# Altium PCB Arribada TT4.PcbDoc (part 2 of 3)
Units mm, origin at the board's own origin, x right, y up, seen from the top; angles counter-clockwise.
Board outline 56 x 35 mm, 6 copper layers (Top Layer, L2GND, L3, L4, L5GND, Bottom Layer), stack 0.865 mm thick; 99 components, 88 nets, 417 pads, 769 vias.
Unrouted connection lines stored in the file: 31.
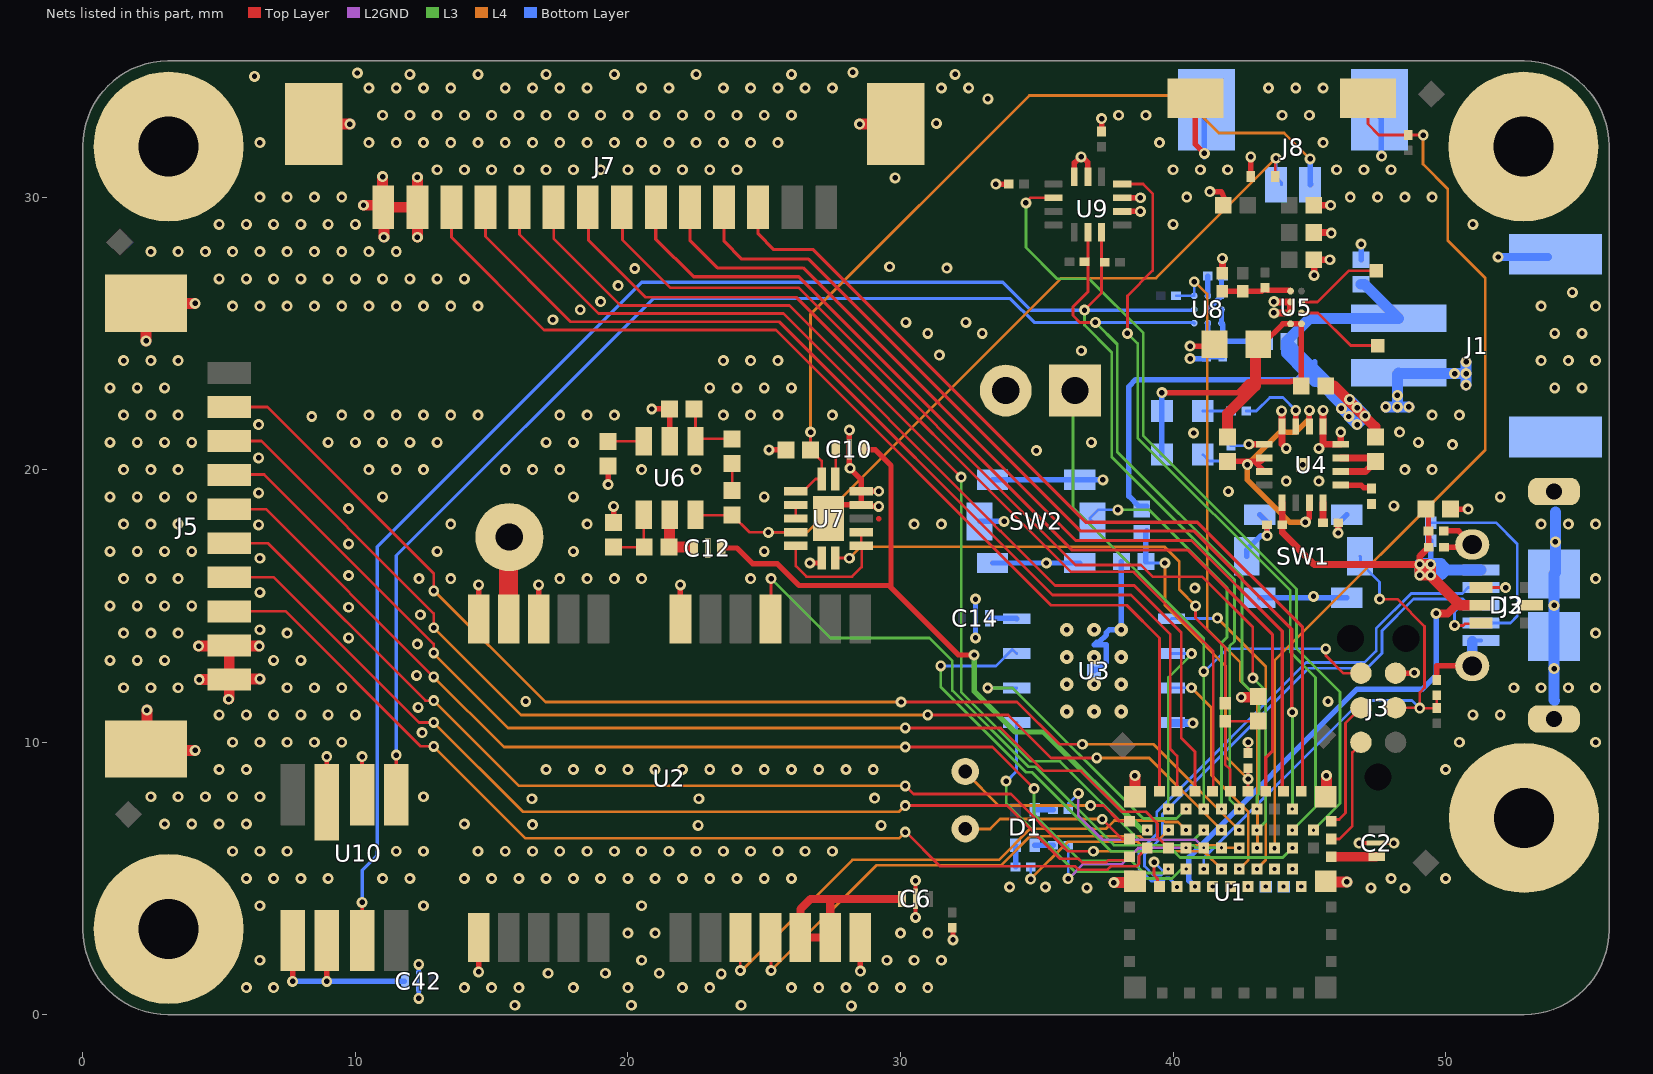
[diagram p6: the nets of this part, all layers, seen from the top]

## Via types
v1: diameter 0.4, hole 0.2, Top Layer to Bottom Layer, tented both sides, 631 vias
v2: diameter 0.23, hole 0.1, Top Layer to L2GND, tented top, 27 vias
v3: diameter 0.25, hole 0.125, L2GND to L3, 25 vias
v4: diameter 0.5, hole 0.2, Top Layer to Bottom Layer, 12 vias
v5: diameter 0.25, hole 0.125, L2GND to L3, tented both sides, 12 vias
v6: diameter 0.23, hole 0.1, Top Layer to L2GND, tented both sides, 12 vias
v7: diameter 0.23, hole 0.1, L5GND to Bottom Layer, tented both sides, 11 vias
v8: diameter 0.25, hole 0.125, L4 to L5GND, tented both sides, 11 vias
v9: diameter 0.3, hole 0.15, L3 to L4, tented both sides, 11 vias
v10: diameter 0.3, hole 0.15, L3 to L4, 11 vias
v11: diameter 0.4, hole 0.2, Top Layer to Bottom Layer, 5 vias
v12: diameter 1, hole 1, Top Layer to Bottom Layer, tented both sides, 1 vias

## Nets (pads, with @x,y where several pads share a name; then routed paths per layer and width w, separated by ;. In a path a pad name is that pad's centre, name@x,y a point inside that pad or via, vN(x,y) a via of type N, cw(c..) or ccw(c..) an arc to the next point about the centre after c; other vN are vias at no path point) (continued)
GND: C1.1 C2.3 C3.1 C4.1 C5.1 C6.3 C8.1 C9.1 C10.3 C11.1 C12.3 C14.3 C19.1 C22.1 C24.1 C30.1 C31.1 C32.1 C33.1 C34.1 C35.1 C36.1 C42.3 C43.1 C45.1 D2.1 D3.2 J1.2 J1.3 J1.4 J2.5 J2.G1 J2.G2 J2.G3 J2.G4 J2.G5 J2.G6 J3.5 J4.2 J5.9 J5.10 J5.11 J5.12 J7.13 J7.14 J7.15 J7.16 J8.3 J8.4 MH1.1 MH2.1 MH3.1 MH4.1 R11.1 R13.1 R18.1 R20.1 R21.1 R22.1 R24.1 R47.1 SW1.1 SW1.G1 SW1.G2 SW1.G3 SW1.G4 SW2.1 SW2.G1 SW2.G2 SW2.G3 SW2.G4 SW3.1 U1.1 U1.7 U1.14 U1.16 U1.18 U1.21 U1.23 U1.24 U1.25 U1.31 U2.7 U2.10 U2.12 U2.13 U2.24 U3.4 U3.9 U4.4 U4.5 U4.8 U4.17 U5.B2 U5.C2 U6.2 U7.7 U7.12 U7.13 U7.15 U8.B2 U8.C1 U9.2 U9.3 U9.6 U9.7 U10.2 U10.3 | length 118.3
  Top Layer w0.1: C45.1@42.75,9.605 v1(42.75,10)
  Top Layer w0.15: U10.3@8.95,7.8 v1(8.95,9.475) ; U10.2@10.25,8.075 v1(10.25,9.475) ; v1(30.55,3.575) C6.3@30.55,4.25 v1(30.55,4.925) ; v1(46.825,6.3) C2.3@47.475,6.3 v1(48.1,6.3)
  Top Layer w0.2: v1(14.525,1.575) U2.13@14.525,2.833 ; U2.12@14.525,14.517 v1(14.525,15.775) ; U2.10@16.725,14.517 v1(16.725,15.775) ; v1(19.275,19.455) R21.1@19.275,20.13 ; R20.1@19.475,18.055 v1(19.475,18.65) ; v1(20.875,22.225) 20.88,22.23 C9.1@21.525,22.23 21.53,22.225 U6.2@21.53,21.045 ; U2.7@21.925,14.517 v1(21.925,15.775) ; v1(25.175,20.725) R22.1@25.8,20.725 ; v1(26.675,16.575) 27.025,16.575 27.109,16.659 U7.7@27.109,16.755 ; U7.15@27.359,18.205 U7.15@27.447,18.294 ; U7.15@27.536,18.205 U7.15@27.447,18.294 ; v1(28.125,21.45) C10.3@28.125,20.75 28.125,20.075 v1(28.15,20.05) 28.559,19.641 U7.13@28.559,19.205 ; v1(28.525,1.6) U2.24@28.525,2.833 ; 29.195,18.205 29.2,18.2 ; v1(29.2,19.205) U7.13@28.559,19.205 ; v1(29.201,18.651) 28.613,18.651 U7.12@28.559,18.705 ; C5.1@31.9,3.195 31.925,3.17 v1(31.925,2.75) ; v1(33.5,30.475) C36.1@33.97,30.475 ; U9.7@36.375,30.738 36.375,31.25 36.6,31.475 v1(36.625,31.475) 36.675,31.475 36.875,31.275 U9.6@36.875,30.738 ; C35.1@37.375,32.405 v1(37.375,32.875) ; U9.2@38.138,29.475 v1(38.8,29.475) ; U9.3@38.138,29.975 v1(38.8,29.975) ; v1(40.625,24.53) 41.455,24.53 C24.1@41.525,24.6 ; SW3.1@40.817,33.627 40.817,31.935 v1(41.15,31.602) ; v1(41.35,30.2) 41.775,30.2 41.91,29.897 C8.1@41.84,29.714 ; U1.14@41.45,4.7 v6(41.455,4.7) ; D2.1@42.85,30.725 v1(42.85,31.475) ; C43.1@43.445,17.975 43.445,17.58 v1(43.45,17.575) ; J3.5@48.16,12.535 48.865,12.535 v1(48.85,12.55) ; C19.1@49.675,12.28 49.675,12.8 J2.G1@50.975,12.8 ; C32.1@49.93,17.75 50.475,17.75 J2.G2@50.975,17.25 50.875,17.15 C31.1@49.935,17.15 ; C30.1@50.175,18.55 v1(50.825,18.55) ; U7.15@27.447,18.294 27.859,18.705 U7.12@28.559,18.705 ; U7.12@28.559,18.705 U7.13@28.559,19.205
  Top Layer w0.25: R13.1@41.809,27.205 v1(41.809,27.75) ; v1(43.7,25.75) U5.B2@44.309,25.75 U5.C2@44.309,26.15 43.7,26.15 v1(43.7,26.165) ; v1(43.982,22.156) 43.986,22.156 44,22.17 U4.8@44,21.582 44,20.932 v11(44.15,20.782) ; C4.1@45.159,28.7 45.775,28.7 v1(45.8,28.675) ; C3.1@45.159,29.7 v1(45.775,29.7) ; v1(45.175,27.125) 45.175,27.684 C1.1@45.159,27.7 v1(45.75,27.7) ; v11(45.35,20.782) 45.5,20.932 ; v1(45.5,22.175) U4.5@45.5,21.582 45.5,20.932 ; v1(46.055,17.675) R11.1@46.055,18.05 ; v1(46.15,21.375) U4.4@46.15,20.932 45.5,20.932
  Top Layer w0.4: J5.12@2.325,9.75 J5.12@2.35,9.775 ; v1(2.325,24.725) J5.11@2.325,26.1 v1@4.1,26.1 ; v1(2.35,11.175) J5.12@2.35,9.775 ; v1(4.125,9.7) 2.425,9.7 J5.12@2.35,9.775 ; v1(4.25,13.525) 5.35,13.525 J5.9@5.375,13.55 ; v1(4.275,12.3) J5.10@5.375,12.3 ; v1(5.35,11.575) 5.375,11.6 J5.10@5.375,12.3 ; v1(6.475,13.525) 5.4,13.525 J5.9@5.375,13.55 ; v1(6.5,12.325) J5.10@5.4,12.325 ; J7.15@8.475,32.675 v1(9.8,32.675) ; v1(10.3,29.7) 10.95,29.7 J7.14@11,29.65 ; v1(11,30.75) J7.14@11,29.65 ; v1(11.05,28.525) 11.05,29.6 J7.14@11.025,29.625 ; v1(12.275,28.525) J7.13@12.275,29.625 ; v1(12.275,30.725) J7.13@12.275,29.625 ; v1(28.5,32.675) J7.16@29.825,32.675 ; v1(37.825,4.85) 38.55,4.85 U1.7@38.6,4.9 ; U1.1@38.6,8 v1(38.6,8.775) ; v1(42.5,11.65) 43.1,11.65 C11.1@43.125,11.675 ; U1.25@45.6,4.9 45.625,4.875 v1(46.375,4.875) ; U1.31@45.6,8 45.625,8.025 v1(45.625,8.775) ; J5.10@5.375,12.3 J5.10@5.4,12.325 ; J5.9@5.375,13.55 5.375,12.35 J5.10@5.4,12.325 ; J7.14@11,29.65 J7.14@11.025,29.625 ; J7.14@11.025,29.625 J7.13@12.275,29.625
  Bottom Layer w0.1: U3.4@39.94,10.72 U3.4@39.96,10.7
  Bottom Layer w0.15: v1(12.325,0.6) C42.3@12.325,1.225 v1(12.325,1.85) ; J2.5@50.975,13.7 51,13.725 J2.5@51.3,13.725
  Bottom Layer w0.2: v1(32.75,13.825) C14.3@32.75,14.55 v1@32.75,15.175 ; SW2.1@32.9,18.1 v1(33.8,18.1) ; SW2.G1@33.375,16.575 SW2.G2@36.575,16.575 ; SW2.G4@33.375,19.625 SW2.G3@36.575,19.625 v1(37.425,19.625) ; U3.9@37.1,12.625 37.1,12.675 37.286,12.675 37.55,12.939 37.55,13.575 37.1,13.575 37.2,13.675 37.286,13.675 37.55,13.939 37.55,14.025 37.65,14.125 v4(38.1,14.125) R47.1@38.1,16.625 ; v1(40.625,24.075) 41.155,24.075 C33.1@41.225,24.145 C34.1@41.825,24.145 ; v1@41.15,31.475 41.15,33.125 J8.3@41.225,33.2 ; U8.B2@41.275,25.875 U8.C1@41.775,26.375 R24.1@41.775,27.045 ; v1(41.809,27.75) 41.83,27.729 R24.1@41.83,27.1 ; SW1.1@42.7,16.825 42.7,17.05 43.225,17.575 v1(43.45,17.575) 43.45,18.075 SW1.G4@43.175,18.35 ; SW1.G1@43.175,15.3 SW1.G2@46.375,15.3 ; v1(46.055,17.675) 46.055,18.03 SW1.G3@46.375,18.35 ; C22.1@46.9,27.7 v1(46.9,28.275) ; J8.4@47.575,33.2 47.575,32.95 47.64,32.885 47.64,31.51 v1@47.675,31.475
  Bottom Layer w0.3: U3.4@39.96,10.7 v1(40.725,10.7) ; v1(51.925,27.8) J1.4@53.75,27.8
  Bottom Layer w0.4: v1(47.8,22.3) v1(48.225,22.3) ; v1(48.65,22.3) v1(48.225,22.3) ; v1(50.75,23.1) v1(50.75,23.525) ; v1(50.75,23.95) v1(50.75,23.525) ; J2.G1@50.975,12.8 J2.5@50.975,13.7 ; 54,11.525 53.975,11.55 J2.G5@53.975,13.875 J2.G6@53.975,16.175 54.025,16.225 54.025,18.45 ; v1(48.225,22.3) v1(48.225,22.725) 48.225,23.5 J1.2@48.275,23.55 48.3,23.525 v1(50.325,23.525) v1(50.75,23.525)
  other v1: 28.2,0.325 15.85,0.35 20.125,0.35 24.15,0.35 6,1 7,1 14,1 15,1 16,1 18,1 20,1 22,1 23,1 26,1 27,1 28,1 29,1 30,1 31,1 23.425,1.5 17.075,1.525 19.175,1.525 21.15,1.525 6.5,2 20.5,2 29.5,2 30.5,2 31.5,2 20,3 21,3 30,3 31,3 6.5,4 12.5,4 20.5,4 36.84,4.658 47.259,4.658 48.5,4.642 34,4.689 35.313,4.689 6,5 7,5 8,5 9,5 11,5 12,5 14,5 15,5 16,5 17,5 18,5 19,5 20,5 21,5 22,5 23,5 24,5 25,5 26,5 48,5 50,5 5.5,6 6.5,6 7.5,6 11.5,6 12.5,6 14.5,6 15.5,6 16.5,6 17.5,6 18.5,6 19.5,6 20.5,6 21.5,6 22.5,6 23.5,6 24.5,6 25.5,6 26.5,6 27.5,6 22.575,6.95 29.291,6.95 16.5,6.975 3,7 4,7 5,7 6,7 14,7 16.475,7.927 22.6,7.927 29.05,7.95 2.5,8 3.5,8 4.5,8 5.5,8 6.5,8 12.5,8 5,9 6,9 17,9 18,9 19,9 20,9 21,9 22,9 23,9 24,9 25,9 26,9 27,9 28,9 29,9 50,9 5.5,10 6.5,10 7.5,10 8.5,10 9.5,10 50.5,10 55.5,10 12.447,10.35 5,11 6,11 7,11 8,11 9,11 10,11 51,11 52,11 12.3,11.275 16.25,11.5 45.683,11.5 1.5,12 2.5,12 3.5,12 7.5,12 8.5,12 9.5,12 52.5,12 53.5,12 54.5,12 55.5,12 12.25,12.45 53.975,12.7 1,13 2,13 3,13 7,13 8,13 12.275,13.6 9.75,13.825 1.5,14 2.5,14 3.5,14 7.5,14 55.5,14 6.5,14.125 12.389,14.675 9.75,14.95 1,15 2,15 3,15 4,15 53.975,15.021 32.75,15.25 45.15,15.35 6.5,15.5 40.8,15.658 1.5,16 2.5,16 3.5,16 12.335,16 13.5,16 17.5,16 18.5,16 19.5,16 20.5,16 24.5,16 55.5,16 9.75,16.117 35.35,16.575 6.5,16.75 1,17 2,17 3,17 4,17 13,17 18,17 25,17 9.75,17.275 54.025,17.35 6.45,17.975 1.5,18 2.5,18 3.5,18 13.5,18 18.5,18 30.5,18 31.5,18 53.5,18 54.5,18 55.5,18 9.75,18.575 48.1,18.667 1,19 2,19 3,19 4,19 11,19 18,19 25,19 52,19 6.45,19.15 42.025,19.2 1.5,20 2.5,20 3.5,20 10.5,20 11.5,20 12.5,20 15.5,20 16.5,20 17.5,20 20.5,20 22.5,20 48.5,20 49.5,20 6.45,20.432 34.983,20.7 50.25,20.92 1,21 2,21 3,21 4,21 9,21 10,21 11,21 12,21 13,21 17,21 18,21 37,21 49,21 40.75,21.344 48.309,21.375 6.45,21.65 8.4,21.95 1.5,22 2.5,22 3.5,22 9.5,22 10.5,22 11.5,22 12.5,22 13.5,22 14.5,22 17.5,22 18.5,22 19.5,22 23.5,22 24.5,22 25.5,22 27.5,22 49.5,22 50.5,22 1,23 2,23 3,23 23,23 24,23 25,23 26,23 54,23 55,23 1.5,24 2.5,24 3.5,24 23.5,24 24.5,24 25.5,24 53.5,24 54.5,24 55.5,24 31.423,24.2 36.637,24.362 31,25 33,25 54,25 55,25 30.2,25.4 32.4,25.4 17.25,25.5 18.25,25.867 5.5,26 6.5,26 7.5,26 8.5,26 9.5,26 10.5,26 11.5,26 12.5,26 13.5,26 14.5,26 53.5,26 55.5,26 4.125,26.1 19,26.165 54.65,26.5 19.638,26.75 5,27 6,27 7,27 8,27 9,27 10,27 11,27 12,27 13,27 14,27 20.25,27.38 31.7,27.394 29.6,27.444 2.5,28 3.5,28 4.5,28 5.5,28 6.5,28 7.5,28 8.5,28 9.5,28 10.5,28 11.5,28 5,29 6,29 7,29 8,29 9,29 10,29 40,29 51,29 6.5,30 7.5,30 8.5,30 9.5,30 40.5,30 46.5,30 47.5,30 48.5,30 49.5,30 29.8,30.7 13,31 14,31 15,31 16,31 17,31 18,31 19,31 20,31 21,31 22,31 23,31 24,31 40,31 41,31 42,31 46,31 47,31 48,31 47.65,31.5 6.5,32 10.5,32 11.5,32 12.5,32 13.5,32 14.5,32 15.5,32 16.5,32 17.5,32 18.5,32 19.5,32 20.5,32 21.5,32 22.5,32 23.5,32 24.5,32 25.5,32 39.5,32 45.5,32 31.316,32.7 11,33 12,33 13,33 14,33 15,33 16,33 17,33 18,33 19,33 20,33 21,33 22,33 23,33 24,33 25,33 26,33 38,33 39,33 44,33 45,33 33.208,33.6 10.5,34 11.5,34 12.5,34 13.5,34 15.5,34 16.5,34 17.5,34 18.5,34 20.5,34 21.5,34 23.5,34 24.5,34 25.5,34 26.5,34 27.5,34 31.5,34 32.5,34 43.5,34 44.5,34 45.5,34 6.3,34.425 12,34.5 14.5,34.5 17,34.5 19.5,34.5 22.5,34.5 26,34.5 32,34.5 10.075,34.55 28.25,34.575
  other v4: 36.1,11.125 37.1,11.125 38.1,11.125 36.1,12.125 37.1,12.125 38.1,12.125 36.1,13.125 37.1,13.125 38.1,13.125 36.1,14.125 37.1,14.125
  other v5: 41.455,4.7 42.1,4.7 42.75,4.7 44.701,4.7 43.725,5.35 44.375,5.35
  other v6: 42.1,4.7 42.75,4.7 44.701,4.7 43.725,5.35 44.375,5.35
  other v7: 41.455,4.7 42.1,4.7 42.75,4.7 44.701,4.7 43.725,5.35 44.375,5.35
  other v8: 41.455,4.7 42.1,4.7 42.75,4.7 44.701,4.7 43.725,5.35 44.375,5.35
  other v9: 41.455,4.7 42.1,4.7 42.75,4.7 44.701,4.7 43.725,5.35 44.375,5.35
  other v11: 44.15,19.582 45.35,19.582 44.75,20.182
NetANT1_1: ANT1.1 U2.11 | length 3.4
  Top Layer w0.121: ANT1.1@15.625,17.475 ANT1.1@15.65,17.5
  Top Layer w0.7: U2.11@15.625,14.067 ANT1.1@15.625,17.475
  other v12: 15.65,17.525
NetC2_2: C2.2 U1.26 | length 1.7
  Top Layer w0.35: U1.26@45.8,5.8 C2.2@47.459,5.8
NetC6_1: C6.1 U2.22 U2.23 | length 8.3
  Top Layer w0.3: U2.22@26.325,2.383 U2.22@26.325,2.833 ; U2.23@27.425,2.383 U2.23@27.425,2.833 ; C6.1@30.05,4.25 27.425,4.25 ; U2.22@26.325,2.833 26.325,3.875 26.7,4.25 27.425,4.25 ; U2.22@26.325,2.833 U2.23@27.425,2.833 ; U2.23@27.425,2.833 27.425,4.25
NetC7_1: C7.1 R12.1 R13.2 U5.D2 | length 2.6
  Top Layer w0.2: R13.2@41.809,26.545 R12.1@42.559,26.545 43.25,26.545 C7.1@43.375,26.67 43.47,26.575 44.284,26.575 U5.D2@44.309,26.55
NetC9_2: C9.2 R17.2 U6.1 | length 2.6
  Top Layer w0.1: C9.2@22.425,22.23 22.48,22.175 U6.1@22.48,21.045 22.566,21.13 R17.2@23.825,21.13
NetC10_1: C10.1 U7.14 | length 1.1
  Top Layer w0.1: U7.14@27.609,19.655 27.625,19.671 C10.1@27.625,20.75
NetC10_2: C10.2 C12.1 U1.3 | length 26.4
  Top Layer w0.2: C12.1@23.425,17.125 24,17.125 24.575,16.55 25.475,16.55 26.275,15.75 29.575,15.75 ; C10.2@28.625,20.725 29.075,20.725 29.65,20.15 29.65,15.75 29.575,15.75 ; v1(32.7,13.2) 32.125,13.2 29.575,15.75
  L3 w0.2: v1(32.7,13.2) 32.7,11.875 34.2,10.375 35.25,10.375 38.85,6.775 v6(39.05,6.775)
  other v5: 39.05,6.775
NetC11_2: C11.2 R25.2 U1.40 | length 3.9
  Top Layer w0.1: U1.40@42.1,8.2 42.1,9 41.91,9.19 R25.2@41.91,10.77 43.12,10.77 C11.2@43.125,10.775
NetC12_2: C12.2 R19.2 U6.5 | length 2.1
  Top Layer w0.4: U6.5@21.53,18.345 21.53,17.186 R19.2@21.5,17.155 C12.2@22.35,17.155
NetC14_2: C14.2 U3.8 | length 1
  Bottom Layer w0.2: C14.2@33.25,14.55 34.24,14.55 U3.8@34.26,14.53
NetC19_2: C19.2 J3.3 R10.1 SW1.2 U1.13 | length 19.9
  Top Layer w0.1: v1(47.575,15.25) 48.225,15.25 49.225,14.25 49.225,12 49.05,11.825 v1(49.05,11.25) ; J3.3@48.16,11.265 49.035,11.265 v1(49.05,11.25) ; R10.1@49.675,11.205 49.63,11.25 v1(49.05,11.25) ; R10.1@49.675,11.255 C19.2@49.675,11.72
  Bottom Layer w0.1: v6(41.125,5.35) 41.125,5.75 46.908,11.533 48.767,11.533 v1(49.05,11.25) ; SW1.2@46.85,16.825 46.875,16.8 46.875,16.575 47.575,15.875 v1(47.575,15.25)
  other v5: 41.125,5.35
  other v7: 41.125,5.35
  other v8: 41.125,5.35
  other v9: 41.125,5.35
NetC33_2: C33.2 U8.B3 | length 0.7
  Bottom Layer w0.2: C33.2@41.225,24.705 41.275,24.755 U8.B3@41.275,25.375
NetC34_2: C34.2 R15.1 U8.C2 U8.C3 | length 2.6
  Bottom Layer w0.2: U8.C2@41.775,25.875 U8.C3@41.775,25.375 41.775,25.363 41.825,25.313 C34.2@41.825,24.705 ; C34.2@41.83,24.7 C34.2@41.825,24.705 ; R15.1@43.25,24.7 43.245,24.705 C34.2@41.825,24.705
NetC42_1: C42.1 U10.5 U10.6 | length 7.1
  Top Layer w0.2: v1(7.7,1.225) U10.5@7.7,2.725 ; v1(8.95,1.225) U10.6@8.95,2.725
  Bottom Layer w0.2: v1(7.7,1.225) v1(8.95,1.225) C42.1@11.8,1.225
NetC45_2: C45.2 R46.1 R47.2 U1.38 | length 11.9
  Top Layer w0.1: U1.38@42.75,8.2 C45.2@42.75,9.045
  L4 w0.1: v1(39.7,16.575) 39.7,15.025 41.925,12.8 41.925,9.475 v1(42.75,8.65)
  Bottom Layer w0.1: R47.2@39,16.625 39.05,16.575 v1(39.7,16.575)
  Bottom Layer w0.2: R47.2@39,16.625 39,17.725 R46.1@39.025,17.75
NetD1_2: D1.2 R3.2 | length 0.7
  Bottom Layer w0.2: D1.2@34.925,7.525 R3.2@35.595,7.525
NetD1_3: D1.3 R4.2 | length 0.7
  Bottom Layer w0.2: D1.3@34.925,6.225 R4.2@35.595,6.225
NetD1_4: D1.4 R5.2 | length 0.8
  Bottom Layer w0.2: R5.2@34.22,5.425 34.225,5.43 D1.4@34.225,6.225
NetD2_2: D2.2 J8.1 R16.1 U6.6 U7.5 | length 30.1
  Top Layer w0.1: U6.6@22.48,18.345 22.495,18.33 R16.1@23.825,18.33 24.45,17.705 U7.5@26.159,17.705 ; D2.2@43.75,30.75 43.75,31.45 v1(43.775,31.425)
  L4 w0.1: v1(25.15,17.7) 26.575,17.7 35.9,27.025 39.375,27.025 v1(43.775,31.425)
  Bottom Layer w0.1: v1(43.775,31.425) 43.775,30.65 43.858,30.65 43.975,30.533 J8.1@43.975,30.45
NetD5_2: D5.2 R26.2 | length 1.1
  Bottom Layer w0.1: D5.2@41.091,20.55 41.321,20.32 R26.2@42.125,20.32
NetD6_2: D6.2 R27.2 | length 1
  Bottom Layer w0.1: D6.2@41.091,22.15 R27.2@42.12,22.15
NetJ2_4: J2.4 R14.1 | length 7.6
  Bottom Layer w0.102: R14.1@49.45,18.055 51.845,18.055 52.625,17.275 52.625,14.625 52.375,14.375 J2.4@51.3,14.375
NetJ3_2: J3.2 U1.28 | length 4.2
  Top Layer w0.1: U1.28@45.8,6.45 46.1,6.45 46.575,6.925 46.575,9.624 46.89,9.939 J3.2@46.89,9.995
NetJ3_4: J3.4 U1.30 | length 4.7
  Top Layer w0.1: U1.30@45.8,7.1 45.866,7.166 46.091,7.166 46.325,7.4 46.325,10.7 J3.4@46.89,11.265
NetJ3_6: J3.6 J4.1 U1.43 | length 23.1
  Top Layer w0.1: v1(45.6,13.425) 45.6,13.175 46.24,12.535 J3.6@46.89,12.535
  L3 w0.1: 36.325,21.95 36.325,18.604 41.125,13.804 v2(41.125,7.55) ; J4.1@36.425,22.85 J4.1@36.475,22.9
  Bottom Layer w0.1: v1(41.125,12.6) 41.15,12.6 41.975,13.425 v1(45.6,13.425)
  other v3: 41.125,7.55
NetJ5_2: J5.2 U1.52 | length 43.9
  Top Layer w0.1: J5.2@5.375,22.3 6.775,22.3 12.875,16.2 v1(12.875,15.55) ; v1(30.025,11.475) 34.275,11.475 35.825,9.925 v1(36.675,9.925)
  L4 w0.1: v1(12.875,15.55) 12.875,15.575 16.975,11.475 v1(30.025,11.475) ; v1(36.675,9.925) 39.275,9.925 v10(42.425,6.775)
  other v2: 42.425,6.775
  other v3: 42.425,6.775
NetJ5_3: J5.3 U1.53 | length 42.7
  Top Layer w0.1: J5.3@5.375,21.05 6.55,21.05 12.875,14.725 v1@12.875,14.205 ; v1(31,11) 33.95,11 35.525,9.425 v1(37.2,9.425)
  L4 w0.1: v1(12.875,14.2) 12.875,14.205 16.08,11 v1(31,11) ; v1@37.125,9.425 v1(37.2,9.425) 39.125,9.425 v10(41.775,6.775)
  other v2: 41.775,6.775
  other v3: 41.775,6.775
NetJ5_4: J5.4 U1.64 | length 40.6
  Top Layer w0.1: J5.4@5.375,19.825 6.656,19.825 12.875,13.606 v1(12.875,13.275) ; v1(30.175,10.525) 33.675,10.525 35.25,8.95 36.625,8.95 38.125,7.45 38.15,7.45 39,7.45 39.432,7.018 39.432,6.519 U1.64@39.825,6.125
  L4 w0.1: v1(12.875,13.275) 12.875,13.25 15.6,10.525 v1(30.175,10.525)
NetJ5_5: J5.5 U1.9 | length 40.6
  Top Layer w0.1: J5.5@5.375,18.55 6.725,18.55 v1(12.875,12.4) ; v1(30.175,9.825) 33.375,9.825 v1(34.9,8.3)
  L3 w0.1: v1(34.9,8.3) 34.9,7.35 36.6,5.65 38.475,5.65 38.925,5.2 39.675,5.2 v2(39.825,5.35)
  L4 w0.1: v1(12.875,12.4) 15.45,9.825 v1(30.175,9.825)
  other v3: 39.825,5.35
NetJ5_6: J5.6 U1.15 | length 41.3
  Top Layer w0.1: J5.6@5.375,17.3 6.8,17.3 12.575,11.525 v1(12.875,11.525) ; v1(30.175,8.4) 30.475,8.1 34.05,8.1 36.15,6 v1(37.075,6)
  L4 w0.1: v1(12.875,11.525) 16,8.4 v1(30.175,8.4) ; v1(37.075,6) 41.125,6 v10(41.775,5.35)
  other v2: 41.775,5.35
  other v3: 41.775,5.35
NetJ5_7: J5.7 U1.6 | length 37.6
  Top Layer w0.1: J5.7@5.375,16.05 7.01,16.05 12.335,10.725 v1(12.875,10.725) ; v1(30.175,7.675) 33.9,7.675 35.85,5.725 36.525,5.725 36.65,5.6 37.55,5.6 37.625,5.675 38.275,5.675 U1.6@38.4,5.8
  L4 w0.1: v1(12.875,10.725) 16.15,7.45 29.95,7.45 v1(30.175,7.675)
NetJ5_8: J5.8 U1.5 | length 38.4
  Top Layer w0.1: J5.8@5.375,14.8 7.45,14.8 12.4,9.85 v1(12.875,9.85) ; v1(30.175,6.7) 30.2,6.7 31.45,5.45 36.4,5.45 36.525,5.325 37.6,5.325 37.725,5.45 38.662,5.45 38.75,5.538 38.75,5.825 39.025,6.1 39.05,6.1 39.075,6.075 39.075,6.1 U1.5@39.05,6.125
  L4 w0.1: v1(12.875,9.85) 16.25,6.475 29.95,6.475 v1(30.175,6.7)
NetJ7_3: J7.3 U1.32 | length 33
  Top Layer w0.121: J7.3@24.775,29.625 24.775,28.65 25.35,28.075 26.8,28.075 36.8,18.075 40.892,18.075 44.75,14.217 44.75,8.25 U1.32@44.7,8.2
NetJ7_4: J7.4 U1.33 | length 34.6
  Top Layer w0.121: J7.4@23.525,29.625 23.525,28.375 24.175,27.725 26.625,27.725 36.6,17.75 40.75,17.75 44.35,14.15 44.35,11.125 v1(44.375,11.1)
  L3 w0.102: v2(44.375,7.55) 44.4,7.575 44.375,7.6 v1(44.375,11.1)
  other v3: 44.375,7.55
NetJ7_5: J7.5 U1.34 | length 34.8
  Top Layer w0.121: J7.5@22.275,29.625 22.275,28.41 23.285,27.4 26.425,27.4 36.425,17.4 40.675,17.4 44,14.075 44,8.25 U1.34@44.05,8.2
NetJ7_6: J7.6 U1.36 | length 35.7
  Top Layer w0.121: J7.6@21.025,29.625 21.025,28.457 22.407,27.075 26.275,27.075 36.3,17.05 40.55,17.05 43.645,13.955 43.645,9.67 43.4,9.425 U1.36@43.4,8.2
NetJ7_7: J7.7 U1.51 | length 38
  Top Layer w0.1: J7.7@19.8,29.6 19.8,28.425 21.55,26.675 26.25,26.675 36.425,16.5 38.825,16.5 39.25,16.075 41.067,16.075 42.925,14.217 v1(42.925,12.35)
  Top Layer w0.2: J7.7@19.775,29.625 J7.7@19.8,29.6
  L3 w0.1: v1(42.925,12.35) 43.401,11.874 43.401,7.101 v3(43.075,6.775)
  other v2: 43.075,6.775
NetJ7_8: J7.8 U1.42 | length 35.5
  Top Layer w0.1: J7.8@18.55,29.6 18.55,28.414 20.639,26.325 26.175,26.325 36.25,16.25 38.55,16.25 41.475,13.325 41.475,8.225 U1.42@41.45,8.2
  Top Layer w0.2: J7.8@18.525,29.625 J7.8@18.55,29.6
NetJ7_9: J7.9 U1.54 | length 38.9
  Top Layer w0.1: J7.9@17.275,29.625 17.275,28.475 19.725,26.025 25.925,26.025 v1(32.225,19.725)
  L3 w0.1: v1(32.225,19.725) 32.232,19.725 32.225,19.718 32.225,11.85 34.775,9.3 35.85,9.3 38.725,6.425 40.775,6.425 v2(41.125,6.775)
  other v3: 41.125,6.775
NetJ7_10: J7.10 U1.44 | length 37.3
  Top Layer w0.1: J7.10@16.025,29.625 16.025,28.625 18.925,25.725 25.7,25.725 33.45,17.975 33.45,17.955 33.655,17.75 33.675,17.75 35.675,15.75 38.575,15.75 40.3,14.025 40.3,10.15 40.8,9.65 U1.44@40.8,8.225
NetJ7_11: J7.11 U1.46 | length 38.1
  Top Layer w0.1: J7.11@14.775,29.625 14.775,28.55 17.9,25.425 25.55,25.425 35.575,15.4 38.45,15.4 39.9,13.95 39.9,9.742 40.15,9.492 U1.46@40.15,8.2
NetJ7_12: J7.12 U1.48 | length 38.8
  Top Layer w0.1: J7.12@13.525,29.625 13.525,28.525 16.925,25.125 25.425,25.125 35.525,15.025 38.3,15.025 39.5,13.825 U1.48@39.5,8.2
NetJ8_2: J8.2 R22.2 U7.1 U7.2 | length 30.9
  Top Layer w0.1: U7.2@26.159,19.205 26.43,19.205 26.88,19.655 U7.1@27.109,19.655 27.109,20.316 R22.2@26.7,20.725 v1(26.7,21.375)
  L4 w0.1: v1(26.7,21.375) 26.7,25.7 34.725,33.725 40.3,33.725 41.675,32.35 44.075,32.35 v1(45.025,31.4)
  Bottom Layer w0.2: J8.2@45.025,30.45 45.05,30.475 45.025,30.5 v1(45.025,31.4)
NetL1_1: L1.1 U5.B1 | length 3.3
  Top Layer w0.1: U5.B1@44.709,25.75 45.316,25.75 46.516,24.55 L1.1@47.509,24.55
NetL1_2: L1.2 U5.C1 | length 3.2
  Top Layer w0.1: U5.C1@44.709,26.15 45.3,26.15 46.45,27.3 L1.2@47.459,27.3
NetMH5_1: MH5.1 U1.2 | length 6.8
  Top Layer w0.1: v1(36.975,7.675) 37.45,7.675 38.025,7.1 U1.2@38.4,7.1
  L4 w0.1: MH5.1@32.375,8.925 32.375,8.9 33.6,7.675 v1(36.975,7.675)
NetMH6_1: MH6.1 U1.4 | length 6.5
  Top Layer w0.1: v1@37.375,7.18 37.395,7.18 38.125,6.45 U1.4@38.4,6.45
  L4 w0.1: MH6.1@32.388,6.813 33.288,6.813 33.655,7.18 v1@37.375,7.18
  other v1: 37.4,7.175
NetR1_1: R1.1 U1.20
  other v5: 43.4,4.7
  other v6: 43.4,4.7
  other v7: 43.4,4.7
  other v8: 43.4,4.7
  other v9: 43.4,4.7
NetR1_2: R1.2 U1.22 | length 0
  Bottom Layer w0.2: R1.2@44.05,4.7 R1.2@44.055,4.7
  other v5: 44.05,4.7
  other v6: 44.05,4.7
  other v7: 44.05,4.7
  other v8: 44.05,4.7
  other v9: 44.05,4.7
NetR2_1: R2.1 U1.39 U8.A2 U9.14 U10.7 | length 73
  Top Layer w0.102: v1(36.75,25.85) 37.375,26.475 37.375,27.35 U9.14@37.375,28.713
  Top Layer w0.121: U10.7@10.25,2.725 v1(10.25,4.125)
  L3 w0.102: v1(36.75,25.85) 36.75,25.3 37.748,24.302 37.748,20.461 42.25,15.959 42.25,13.7 42.075,13.525 42.075,7.9 v2(42.425,7.55)
  Bottom Layer w0.121: v1(10.25,4.125) 10.25,5.3 10.8,5.85 10.8,17.175 20.5,26.875 33.75,26.875 34.775,25.85 v1(36.75,25.85) 40.75,25.85 U8.A2@40.775,25.875
  other v3: 42.425,7.55
NetR3_1: R3.1 U1.62 | length 6.8
  L2GND w0.1: v1@36.475,8.1 36.5,8.125 v1(36.525,8.125) 36.525,7.3 37.4,6.425 40.825,6.425 v2(41.125,6.125)
  Bottom Layer w0.1: R3.1@36.155,7.525 36.155,7.755 v1(36.525,8.125) 36.5,8.125 v1@36.475,8.1
NetR4_1: R4.1 U1.63 | length 6
  L2GND w0.1: v1(36.15,4.999) 36.174,4.999 36.7,5.525 38.125,5.525 38.725,6.125 v2(40.475,6.125)
  Bottom Layer w0.1: v1(36.15,4.999) 36.15,5.075 36.155,5.08 R4.1@36.155,6.225
NetR5_1: R5.1 U1.60 | length 8.9
  L4 w0.1: v1(34.775,4.975) 36.15,6.35 38.697,6.35 38.822,6.225 41.75,6.225 41.85,6.125 v2(42.425,6.125)
  Bottom Layer w0.1: v1(34.775,4.975) 34.858,4.975 34.775,5.058 34.775,5.392 34.808,5.425 R5.1@34.78,5.425
  other v3: 42.425,6.125
  other v10: 42.425,6.125
NetR6_1: R6.1 U1.37 U8.A3 U9.13 U10.1 | length 66.9
  Top Layer w0.102: U9.13@36.875,28.713 36.875,26.525 36.325,25.975 36.325,25.65 36.575,25.4 v1(37.15,25.4)
  Top Layer w0.121: U10.1@11.5,8.075 v1(11.5,9.525)
  L3 w0.102: v1@37.15,25.425 37.175,25.4 37.175,25.375 37.95,24.6 37.95,20.65 42.525,16.075 42.525,12.2 43.15,11.575 43.15,8.1 43.075,8.025 v2(43.075,7.55)
  Bottom Layer w0.121: v1(11.5,9.525) 11.5,16.85 20.925,26.275 34.025,26.275 34.9,25.4 v1(37.15,25.4) 40.75,25.4 U8.A3@40.775,25.375
  other v3: 43.075,7.55
NetR7_1: R7.1 U4.2 U4.3 | length 2.8
  Top Layer w0.25: U4.2@46.15,19.932 47.057,19.932 R7.1@47.425,20.3 47.293,20.432 U4.3@46.15,20.432
NetR8_1: R8.1 U4.6 U4.10 U4.11 U4.15 | length 9.9
  Top Layer w0.2: R8.1@42,20.3 42.982,20.3 ; U4.11@43.35,19.932 42.982,20.3 ; U4.10@43.35,20.432 43.218,20.3 42.982,20.3 ; v1(44.85,18.075) 45,18.225 U4.15@45,18.782 ; U4.6@45,21.582 v1(45,22.175)
  L4 w0.2: v1@44.875,18.075 v1(44.85,18.075) 44.275,18.075 42.725,19.625 v1(42.725,20.182) 42.732,20.182 43.925,21.375 44.5,21.375 45,21.875 v1(45,22.175)
NetR11_2: R11.2 U4.16 | length 0.7
  Top Layer w0.25: U4.16@45.5,18.782 45.5,18.102 R11.2@45.52,18.082
NetR16_2: R16.2 R17.1 | length 1
  Top Layer w0.1: R16.2@23.825,19.23 R17.1@23.825,20.23
NetR18_2: R18.2 U4.1 | length 1.2
  Top Layer w0.2: U4.1@46.15,19.432 46.9,19.432 47,19.332 47.248,19.332 R18.2@47.275,19.305
NetR19_1: R19.1 R20.2 U6.4 | length 2.3
  Top Layer w0.1: R20.2@19.475,17.155 R19.1@20.6,17.155 20.58,17.175 U6.4@20.58,18.345
NetR21_2: R21.2 U6.3 | length 1.3
  Top Layer w0.1: R21.2@19.29,21.045 U6.3@20.58,21.045
NetR23_1: R23.1 U1.59 U8.A1 | length 22.9
  L4 w0.1: v1(40.774,26.891) 40.808,26.891 41.25,26.449 41.25,14.15 42.475,12.925 42.475,12.25 43.1,11.625 43.1,6.15 v2(43.075,6.125)
  Bottom Layer w0.1: R23.1@40.125,26.375 U8.A1@40.774,26.378 ; U8.A1@40.775,26.375 U8.A1@40.775,26.375 U8.A1@40.774,26.378 ; v1(40.774,26.891) U8.A1@40.774,26.378
  other v3: 43.075,6.125
  other v10: 43.075,6.125
NetR24_2: R24.2 U8.B1 | length 0.7
  Bottom Layer w0.2: U8.B1@41.275,26.375 R24.2@41.275,27.095
NetR25_1: R25.1 U7.8 | length 18.9
  Top Layer w0.1: U7.8@27.609,16.755 28.105,16.755 28.11,16.751 v1(28.126,16.751) ; v1(40.825,15) 40.825,14.554 41.91,13.469 R25.1@41.91,11.43
  L4 w0.1: v1(28.126,16.751) 28.551,17.175 39.675,17.175 40.225,16.625 40.225,15.6 v1(40.825,15)
NetR26_1: R26.1 U4.9 | length 1.2
  Top Layer w0.25: v1(42.782,20.932) U4.9@43.35,20.932
  Bottom Layer w0.1: R26.1@42.125,20.88 42.73,20.88 v1(42.782,20.932)
NetR27_1: R27.1 U4.7 | length 2.8
  Top Layer w0.2: U4.7@44.5,21.582 v1@44.5,22.125
  Bottom Layer w0.1: R27.1@42.68,22.15 43.05,22.15 43.55,22.65 44.025,22.65 v1(44.5,22.175)
NetR35_1: R35.1 SW3.2 U1.58 | length 33.3
  Top Layer w0.1: SW3.2@47.147,33.5 47.147,32.678 47.545,32.28 R35.1@48.625,32.28 49.17,32.28 v1(49.175,32.275)
  L4 w0.1: v10@43.725,6.125 43.725,13 51.45,20.725 51.45,27.025 50.075,28.4 50.075,30.3 49.17,31.205 v1@49.17,32.28
  other v2: 43.726,6.111
  other v3: 43.726,6.111
  other v10: 43.726,6.111
NetSW2_2: SW2.2 U1.41 | length 14.7
  L3 w0.1: v1(37.975,18.525) 39.125,18.525 41.975,15.675 41.975,13.85 41.775,13.65 v2(41.775,7.55)
  Bottom Layer w0.1: SW2.2@37.05,18.1 36.938,18.212 37.25,18.525 v1(37.975,18.525)
  other v3: 41.775,7.55
NetU1_11: U1.11 U3.5 | length 11
  L3 w0.102: v1(33.875,8.575) 33.875,7.775 36.4,5.25 38.5,5.25 38.751,4.999 39.953,4.999 40.304,5.35 v2(40.475,5.35)
  Bottom Layer w0.121: v1(33.875,8.575) 33.9,8.575 34.255,8.93 34.255,10.725 U3.5@34.26,10.72
  other v3: 40.475,5.35
NetU1_17: U1.17 U3.3 | length 8.4
  L3 w0.102: v10@42.421,5.354 v2(42.425,5.35)
  L4 w0.102: v1(40.675,12) 41.4,11.275 41.4,8.8 42.759,7.441 42.759,5.684 v2(42.425,5.35)
  Bottom Layer w0.102: U3.3@39.94,11.99 39.95,12 v1(40.675,12)
  other v3: 42.425,5.35
  other v10: 42.425,5.35
NetU1_19: U1.19 U3.1 | length 11.8
  L4 w0.102: v1@41.6,14.55 v1(41.625,14.55) 43.4,12.775 43.4,5.675 v2(43.075,5.35) v10@43.091,5.35
  Bottom Layer w0.102: U3.1@39.94,14.53 39.952,14.542 41.592,14.542 v1@41.6,14.55
  other v3: 43.075,5.35
  other v10: 43.075,5.35
NetU1_29: U1.29 U9.9 | length 30
  Top Layer w0.1: v1(34.6,29.788) 34.6,29.8 34.775,29.975 U9.9@35.613,29.975
  L3 w0.1: v1(34.6,29.788) 34.6,28.15 35.75,27 36.925,27 38.9,25.025 38.9,21.249 44.525,15.624 44.525,13.442 46.125,11.842 46.125,7.75 v2(45.15,6.775)
  other v3: 45.15,6.775
NetU1_45: U1.45 U3.6 | length 10.5
  L3 w0.102: v1(33.2,11.99) 34.114,11.99 38.905,7.199 40.124,7.199 v2(40.475,7.55)
  Bottom Layer w0.102: v1(33.2,11.99) 34.23,11.99 34.245,11.975 U3.6@34.26,11.99
  other v3: 40.475,7.55
NetU1_47: U1.47 U3.2 | length 7
  L3 w0.102: v2(39.825,7.55) 39.825,12.375 40.675,13.225 v1(40.675,13.25) v1@40.774,13.25
  Bottom Layer w0.102: U3.2@39.94,13.26 39.95,13.25 v1(40.675,13.25) v1@40.774,13.25
  other v3: 39.825,7.55
NetU1_49: U1.49 U9.4 | length 28.2
  Top Layer w0.1: U9.4@38.138,30.475 38.9,30.475 39.25,30.125 39.25,27.3 38.325,26.375 v1(38.325,25)
  L3 w0.1: v1(38.325,25) 38.7,24.625 38.7,21.166 44.3,15.566 44.3,13.3 45.225,12.375 45.225,7.625 v2(44.375,6.775)
  other v3: 44.375,6.775
NetU1_55: U1.55 U2.20 | length 20
  Top Layer w0.1: v1(24.125,1.625) U2.20@24.125,2.833
  L4 w0.1: v1(24.125,1.625) 24.175,1.625 28.234,5.684 33.609,5.684 34.75,6.825 37.545,6.825 37.845,7.125 39.651,7.125 39.701,7.075 40.175,7.075 v2(40.475,6.775)
  other v3: 40.475,6.775
  other v10: 40.475,6.775
NetU1_56: U1.56 U2.21 | length 18
  Top Layer w0.1: U2.21@25.225,2.833 25.25,2.808 v1(25.25,1.625)
  L2GND w0.1: v1@25.275,1.625 v1@25.292,1.625
  L4 w0.1: v1(25.25,1.625) 29.109,5.484 33.692,5.484 34.758,6.55 38.78,6.55 38.905,6.425 39.475,6.425 v2(39.825,6.775)
  other v3: 39.825,6.775
  other v10: 39.825,6.775
NetU1_57: U1.57 U3.7 | length 19.5
  L3 w0.102: v1(31.475,12.8) 31.475,12.033 34.609,8.899 34.826,8.899 37.725,6 40.028,6 40.253,5.774 44.024,5.774 v2(44.375,6.125)
  Bottom Layer w0.102: v1(31.475,12.8) 33.5,12.8 34.1,13.4 34.25,13.25 U3.7@34.26,13.26
  other v3: 44.375,6.125
  other v10: 44.375,6.125
NetU1_61: U1.61 U2.4 | length 22.7
  Top Layer w0.1: U2.4@25.225,14.517 25.25,14.542 v1(25.25,16)
  L3 w0.1: v1(25.25,16) 27.425,13.825 31.056,13.825 31.9,12.981 31.9,11.892 34.692,9.1 34.95,9.1 37.825,6.225 40.75,6.225 40.85,6.125 v2(41.775,6.125)
  other v3: 41.775,6.125
NetU7_3: U7.3 U7.4 | length 0.5
  Top Layer w0.1: U7.4@26.159,18.205 U7.3@26.159,18.705
NetU7_6: U7.6 U7.9 U7.10 | length 4.7
  Top Layer w0.1: U7.6@26.159,17.205 26.159,16.466 26.55,16.075 28.225,16.075 28.575,16.425 28.575,17.189 U7.9@28.559,17.205 U7.10@28.559,17.705
USB_D_N: D3.4 J2.2 U1.10 | length 21.8
  Top Layer w0.102: v6(40.15,4.689) 40.153,4.689 40.157,4.693 U1.10@40.15,4.7 ; D3.4@51.3,15.675 v1(52.2,15.675)
  Bottom Layer w0.102: v6(40.15,4.689) 40.15,4.72 39.841,5.028 39.757,5.028 39.636,4.907 39.197,4.907 38.737,5.367 38.737,5.966 39.401,6.63 39.401,7.444 44.882,12.925 47.025,12.925 47.45,13.35 47.45,14.175 48.735,15.46 50.61,15.46 50.825,15.675 J2.2@51.3,15.675 v1(52.2,15.675)
  other v5: 40.15,4.689
  other v7: 40.15,4.689
  other v8: 40.15,4.689
  other v9: 40.15,4.689
USB_D_P: D3.6 J2.3 U1.8 | length 22.2
  Top Layer w0.102: v1@39.3,5.624 v1(39.3,5.6) 39.3,5.125 39.432,4.993 39.432,4.769 U1.8@39.5,4.7 ; v1(50.325,14.286) 50.653,14.286 50.717,14.35 51.275,14.35 D3.6@51.3,14.375
  Bottom Layer w0.102: v1(39.3,5.6) 39.609,5.291 39.609,5.177 39.549,5.117 39.284,5.117 38.947,5.454 38.947,5.879 39.611,6.543 39.611,7.357 44.969,12.715 47.112,12.715 47.66,13.263 47.66,14.088 48.822,15.25 50.625,15.25 J2.3@50.85,15.025 ; v1(50.325,14.286) 50.325,14.775 50.575,15.025 J2.3@50.85,15.025 ; J2.3@51.3,15.025 J2.3@50.85,15.025
VBAT: C22.2 J1.1 R7.2 R9.2 R15.2 R46.2 | length 30.5
  Top Layer w0.4: R9.2@45.6,23.075 45.9,23.075 46.725,22.25 47.4,21.575 47.4,21.225 R7.2@47.425,21.2
  Bottom Layer w0.2: R46.2@39.025,18.65 38.75,18.65 38.375,19.025 38.375,23.05 38.625,23.3 44.55,23.3 44.837,23.588 45.05,23.8 45.2,23.95 45.2,23.8 45.2,23.65 45.2,23.225 v1(46.175,22.25)
  Bottom Layer w0.4: 45.2,23.225 44.837,23.588 44.15,24.275 R15.2@44.15,24.7 ; v1(46.175,22.25) 46.45,21.975 v1(46.45,21.95) v1(46.75,21.65) 47.043,21.943 v1(47.043,21.975) 47.043,21.982 v1(46.75,22.275) 46.75,22.3 v1(46.475,22.575) 46.275,22.575 45.2,23.65 45.05,23.8 R15.2@44.15,24.7 ; C22.2@46.9,26.8 47.025,26.8 J1.1@48.275,25.55 45,25.55 R15.2@44.15,24.7
VBUS: C30.2 C31.2 C32.2 C43.2 D3.5 J2.1 R14.2 U1.12 U4.13 | length 34.8
  Top Layer w0.2: C30.2@49.275,18.55 49.37,18.455 C32.2@49.37,17.75 ; C31.2@49.375,17.15 C32.2@49.375,17.775
  Top Layer w0.25: U4.13@44,18.782 44.005,18.777 C43.2@44.005,18.082 ; C43.2@44.005,17.975 44.005,17.695 45.175,16.525 v1(49.05,16.525) 49.05,16.825 C31.2@49.375,17.15
  Top Layer w0.3: 49.25,16.15 49.275,16.125 v1@49.425,16.125 ; v1(49.65,14.725) 50.075,14.725 50.375,15.025
  Top Layer w0.4: 49.25,16.15 v1@49.05,16.15 ; v1@49.275,16.125 v1(49.05,16.125) v1@49.05,16.15 ; D3.5@51.3,15.025 50.525,15.025 49.425,16.125 v1(49.45,16.125) v1(49.45,16.525) v1(49.05,16.525) v1@49.05,16.15
  Bottom Layer w0.2: v7(40.8,4.7) 40.575,4.925 40.575,5.775 46.75,11.95 49.15,11.95 49.65,12.45 49.65,14.225 v1(49.65,14.725) ; v1@49.45,16.55 R14.2@49.45,17.395
  Bottom Layer w0.3: v1@49.45,16.15 49.45,16.325 ; 50.025,16.325 50.05,16.325
  Bottom Layer w0.4: v1(49.05,16.125) v1@49.05,16.15 ; v1(49.45,16.125) v1@49.45,16.15 ; 49.45,16.325 v1(49.45,16.525) v1@49.45,16.55 ; J2.1@51.3,16.325 50.05,16.325 49.825,16.55 v1@49.45,16.55 ; v1@49.05,16.15 v1@49.45,16.15 ; v1@49.05,16.15 v1(49.05,16.525) 49.05,16.55 v1@49.45,16.55 ; v1@49.45,16.15 49.85,16.15 50.025,16.325 49.675,16.325 v1@49.45,16.55
  other v5: 40.8,4.7
  other v6: 40.8,4.7
  other v8: 40.8,4.7
  other v9: 40.8,4.7
VSYS: C24.2 D5.1 D6.1 R8.2 R9.1 U5.A1 U5.A2 | length 15.7
  Top Layer w0.2: v1(39.591,22.825) 42.375,22.825 42.775,23.225 43.025,23.225 44.3,23.225 44.325,23.25 44.525,23.25 R9.1@44.7,23.075 ; C24.2@43.125,24.6 43.275,24.6 44.025,25.35 U5.A2@44.309,25.35 U5.A1@44.709,25.35 44.709,23.059 R9.1@44.7,23.05
  Top Layer w0.4: R8.2@42,21.2 42,22.05 43.025,23.075 43.025,23.225 43.025,24.5 C24.2@43.125,24.6
  Bottom Layer w0.2: D5.1@39.591,20.55 D6.1@39.591,22.15 v1@39.591,22.809
pads on no net: D3.1 D3.3 FID1.1 FID2.1 FID3.1 FID4.1 FID5.1 FID6.1 FID7.1 FID8.1 FID10.1 FID11.1 J3.H1 J3.H2 J3.H3 U1.27 U1.35 U1.50 U1.65 U1.66 U1.67 U1.68 U1.69 U1.70 U1.71 U1.72 U1.73 U1.74 U1.75 U1.76 U1.77 U1.78 U2.1 U2.2 U2.3 U2.5 U2.6 U2.8 U2.9 U2.14 U2.15 U2.16 U2.17 U2.18 U2.19 U4. U4.12 U4.14 U7.11 U9. U9.10 U9.11 U10. U10.4 U10.8
copper on no net: | length 0

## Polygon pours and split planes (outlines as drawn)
DCDC_3V3 on L5GND "L5_DCDC_3V3" (solid, pour order 20): 42.325,29.525 41.558,28.758 34.55,28.758 34.55,30.259 35.128,30.259 35.128,32.175 36.99,32.173 36.99,31.308 37.775,31.308 37.775,32.525 35.128,32.525 26.75,32.525 18.975,24.75 5.1,24.75 4.075,23.725 4.075,23.375 4.45,23 21.775,23 24.5,25.725 50.15,25.725 51.475,24.4 51.475,21.325 46.8,16.65 41.219,16.65 40.494,17.375 38.825,17.375 38.1,16.65 30.1,16.65 28.325,14.875 23.4,14.875 22.272,14.875 20.45,14.875 13,14.875 13,1.136 13.125,1.025 13.3,1.025 13.45,1.136 13.45,12.6 30.6,12.6 30.6,3.825 32.125,3.825 32.125,4.5 33.65,4.5 33.65,14.875 46.8,14.875 46.8,7.1 49.2,7.1 49.2,17.119 52.75,20.669 52.75,25.95 49.175,29.525
GND on L5GND "L5_GND" (solid, pour order 22): 0.125,34.875 0.125,0.125 55.875,0.125 55.875,34.875
GND on L2GND "L2_GND" (solid, pour order 12): 0.125,34.875 0.125,0.125 55.875,0.125 55.875,34.875
GND on L4 "L4_GND" (solid, pour order 18): 0.125,34.875 0.125,0.125 55.875,0.125 55.875,34.875
GND on L3 "L3_GND" (solid, pour order 16): 0.125,34.875 0.125,0.125 55.875,0.125 55.875,34.875
GND on Top Layer "L1_GND" (solid, pour order 8): 0.125,34.875 0.125,0.125 55.875,0.125 55.875,34.875
GND on Bottom Layer "BOTGND" (solid, pour order 24): 0.125,34.875 0.125,0.125 55.875,0.125 55.875,34.875

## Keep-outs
L2GND:
  circle w0.1: c15.65,17.525 r1.275
L5GND:
  circle w0.1: c15.65,17.525 r1.275
Bottom Layer:
  circle w0.1: c15.65,17.525 r1.275

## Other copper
Top Layer:
  pour cut-out: 46.625,26.825 49.125,26.825 49.125,24.875 46.65,24.875
  pour cut-out: 46.489,12.925 48.541,12.925 48.541,9.605 46.5,9.605
  region net VBUS: 49.05,15.925 45.55,15.925 43.85,17.625 43.85,18.4 43.9,18.45 44.125,18.45 44.35,18.225 44.35,17.825 45.45,16.725 49.05,16.725
  region net VBAT: 45.4,22.825 45.85,22.375 45.85,22.25 47.168,20.932 47.7,20.932 47.7,21.625 45.95,23.375 45.4,23.375
  region net NetR7_1: 45.875,20.55 45.875,19.825 47.525,19.825 47.7,20 47.7,20.425 47.575,20.55
  region net NetR8_1: 42,20.2 42.375,19.825 43.625,19.825 43.625,20.55 43.025,20.55 42.975,20.6 42,20.6
  region net VSYS: 44.825,25.35 45,25.175 45,22.825 43.64,22.825 42.29,21.475 41.7,21.475 41.7,23.3 43.875,25.475 44.709,25.475
  region net DCDC_3V3: 42.375,29.305 42.6,29.69 42.6,30 43.375,30 44.25,30 44.35,29.9 44.35,27.425 44.35,27.795 44.839,26.964 44.562,26.812 43.925,27.045 43.6,27.045 42.375,27.045
  region net NetL1_1: 44.709,25.625 44.875,25.625 46.2,24.3 46.65,24.75 46.65,25.875 44.709,25.875
  region net NetL1_2: 44.709,26.275 44.95,26.275 46.25,27.575 46.65,27.575 46.65,26.025 44.7,26.025
  pour cut-out: 35.95,30.4 35.95,29.05 37.8,29.05 37.8,30.4
  pour cut-out: 56,0 56,4.45 32.125,4.45 32.125,0
L2GND:
  pour cut-out: 15.225,13.625 16.025,13.625 16.025,16.25 15.225,16.25
  pour cut-out: 35.95,30.4 35.95,29.05 37.8,29.05 37.8,30.4
  pour cut-out: 56,0 56,4.45 32.125,4.45 32.125,0
L3:
  pour cut-out: 35.95,30.4 35.95,29.05 37.8,29.05 37.8,30.4
  pour cut-out: 56,0 56,4.45 32.125,4.45 32.125,0
L4:
  pour cut-out: 35.95,30.4 35.95,29.05 37.8,29.05 37.8,30.4
  pour cut-out: 56,0 56,4.45 32.125,4.45 32.125,0
L5GND:
  pour cut-out: 35.95,30.4 35.95,29.05 37.8,29.05 37.8,30.4
  pour cut-out: 56,0 56,4.45 32.125,4.45 32.125,0
Bottom Layer:
  region net VBAT: 45.975,27.075 43.95,25.05 43.95,24.175 46.6,21.525 46.9,21.525 47.175,21.8 47.175,22.125 46.5,22.8 46.35,22.8 46.05,23.1 46.05,24.85 46.25,25.05 47.45,25.05 48.2,25.8 48.2,26.075 47.2,27.075
  pour cut-out: 15.6,19
  pour cut-out: 35.95,30.4 35.95,29.05 37.8,29.05 37.8,30.4
  region: 50.125,26.025
  pour cut-out: 56,0 56,4.45 32.125,4.45 32.125,0

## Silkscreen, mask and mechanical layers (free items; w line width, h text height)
Top Overlay:
  circle w0.1: c31.075,26.94 r0.451
  lines w0.1: 30.8,24.44 31.075,23.94 ; 31.075,26.915 31.075,23.94 ; 31.075,26.94 34.075,26.94 ; 31.35,24.44 31.075,23.94 ; 33.575,26.665 34.075,26.94 ; 33.575,27.215 34.075,26.94
  text "GND" at 10.725,28.15 h0.6 r270
  text "GND" at 11.973,28.15 h0.6 r270
  text "EXT2_GPIO6" at 13.321,28.15 h0.6 r270
  text "EXT2_GPIO5" at 14.569,28.15 h0.6 r270
  text "EXT2_GPIO4" at 15.817,28.15 h0.6 r270
  text "EXT2_GPIO3" at 17.065,28.15 h0.6 r270
  text "EXT2_GPIO2" at 18.313,28.15 h0.6 r270
  text "EXT2_GPIO1" at 19.561,28.15 h0.6 r270
  text "CS" at 20.71,28.15 h0.6 r270
  text "MOSI" at 21.958,28.15 h0.6 r270
  text "MISO" at 23.206,28.15 h0.6 r270
  text "CLK" at 24.454,28.15 h0.6 r270
  text "3V3" at 25.702,28.15 h0.6 r270
  text "3V3" at 26.95,28.15 h0.6 r270
  text "Z" at 29.825,27.65 h1
  text "Y" at 34.225,26.575 h1
  text "X" at 31.675,23.825 h1
  text "3V3" at 6.8,23.225 h0.6
  text "EXT1_GPIO1" at 6.8,22.078 h0.6
  text "EXT1_GPIO2" at 6.8,20.831 h0.6
  text "EXT1_GPIO3" at 6.8,19.583 h0.6
  text "CTS" at 6.75,18.25 h0.6
  text "RTS" at 6.8,16.989 h0.6
  text "TX" at 6.8,15.775 h0.6
  text "RX" at 6.8,14.5 h0.6
  text "GND" at 6.8,13.247 h0.6
  text "GND" at 6.8,12 h0.6
  text "NFC" at 31.4,7.225 h0.6 r90
Bottom Overlay:
  region: 20.975,2.65 17,2.65 17,0.5 20.975,0.5
  text "ARRIBADA HORIZON" at 28.85,32.059 h1.2
  text "Salt" at 39.525,31.35 h1
  text "Water" at 39.525,30 h1
  text "Switch" at 39.575,28.7 h1
  text "+" at 45.5,25.1 h1
  text "GND" at 34.375,24.6 h0.8
  text "DBG" at 38,24.575 h0.8
  text "-" at 45.55,23.025 h1
  text "PGOOD" at 41.95,22.9 h0.7
  text "BOOT" at 36.491,20.3 h0.7
  text "CHG" at 41.25,19.125 h0.7
  text "RESET" at 45.6,13.9 h0.7
  text "ARRIBADA.ORG" at 2.15,10.6 h1.2 r270
  text "PCB REV 4.1" at 30.225,3.225 h1
  text "DESIGN PARTNERS:" at 52.7,2.725 h1
  text "BUILD REV" at 30.225,1.009 h1
  text "icoteq.com | zsl.org" at 52.625,0.975 h1.1
Mechanical 12:
  lines w0.1: 3.125,35 ccw(c3.15,31.85) 0,31.875 0,3.125 ccw(c3.15,3.15) 3.125,0 52.875,0 ccw(c52.85,3.15) 56,3.125 56,31.875 ccw(c52.85,31.85) 52.875,35 3.15,35
Mechanical 16:
  drawing of 496 lines, arcs and shapes, not listed
  text "1" at -75.963,178.511 h1.78
  text "2" at -26.924,178.511 h1.78
  text "3" at 22.335,178.511 h1.78
  text "4" at 71.628,178.511 h1.78
  text "5" at 120.904,178.511 h1.78
  text "6" at 169.926,178.511 h1.78
  text "7" at 219.456,178.511 h1.78
  text "8" at 268.478,178.511 h1.78
  text "A" at -98.095,144.526 h1.78
  text "A" at 290.525,144.526 h1.78
  text "Layer" at -84.16,106.868 h1.52
  text "Name" at -73.749,106.868 h1.52
  text "Material" at -50.133,106.868 h1.52
  text "Thickness" at -21.439,106.868 h1.52
  text "Constant" at -4.934,106.868 h1.52
  text "Board Layer Stack" at 9.541,106.868 h1.52
  text "1" at -84.16,103.82 h1.52
  text "Top Overlay" at -73.749,103.82 h1.52
  text "2" at -84.16,100.772 h1.52
  text "Top Solder" at -73.749,100.772 h1.52
  text "Solder Resist" at -50.133,100.772 h1.52
  text "0.020mm" at -21.439,100.772 h1.52
  text "4.1" at -4.934,100.772 h1.52
  text "3" at -84.16,97.724 h1.52
  text "Top Layer" at -73.749,97.724 h1.52
  text "Copper" at -50.133,97.724 h1.52
  text "0.012mm" at -21.439,97.724 h1.52
  text "4" at -84.16,94.676 h1.52
  text "Dielectric1" at -73.749,94.676 h1.52
  text "EM-827B-1080_RC68" at -50.133,94.676 h1.52
  text "0.086mm" at -21.439,94.676 h1.52
  text "3.8" at -4.934,94.676 h1.52
  text "5" at -84.16,91.628 h1.52
  text "L2GND" at -73.749,91.628 h1.52
  text "Copper" at -50.133,91.628 h1.52
  text "0.012mm" at -21.439,91.628 h1.52
  text "6" at -84.16,88.58 h1.52
  text "Dielectric2" at -73.749,88.58 h1.52
  text "EM-827B-106RC76" at -50.133,88.58 h1.52
  text "0.064mm" at -21.439,88.58 h1.52
  text "3.7" at -4.934,88.58 h1.52
  text "7" at -84.16,85.532 h1.52
  text "Dielectric3" at -73.749,85.532 h1.52
  text "EM-827B-106RC76" at -50.133,85.532 h1.52
  text "0.064mm" at -21.439,85.532 h1.52
  text "3.7" at -4.934,85.532 h1.52
  text "8" at -84.16,82.484 h1.52
  text "L3" at -73.749,82.484 h1.52
  text "Copper" at -50.133,82.484 h1.52
  text "0.017mm" at -21.439,82.484 h1.52
  text "9" at -84.16,79.436 h1.52
  text "Dielectric4" at -73.749,79.436 h1.52
  text "EM827B" at -50.133,79.436 h1.52
  text "0.355mm" at -21.439,79.436 h1.52
  text "4.4" at -4.934,79.436 h1.52
  text "10" at -84.16,76.388 h1.52
  text "L4" at -73.749,76.388 h1.52
  text "Copper" at -50.133,76.388 h1.52
  text "0.017mm" at -21.439,76.388 h1.52
  text "B" at -98.095,73.914 h1.78
  text "B" at 290.525,73.914 h1.78
  text "11" at -84.16,73.34 h1.52
  text "Dielectric5" at -73.749,73.34 h1.52
  text "EM-827B-106RC76" at -50.133,73.34 h1.52
  text "0.064mm" at -21.439,73.34 h1.52
  text "3.7" at -4.934,73.34 h1.52
  text "12" at -84.16,70.292 h1.52
  text "Dielectric6" at -73.749,70.292 h1.52
  text "EM-827B-106RC76" at -50.133,70.292 h1.52
  text "0.064mm" at -21.439,70.292 h1.52
  text "3.7" at -4.934,70.292 h1.52
  text "13" at -84.16,67.244 h1.52
  text "L5GND" at -73.749,67.244 h1.52
  text "Copper" at -50.133,67.244 h1.52
  text "0.012mm" at -21.439,67.244 h1.52
  text "14" at -84.16,64.196 h1.52
  text "Dielectric7" at -73.749,64.196 h1.52
  text "EM-827B-1080_RC68" at -50.133,64.196 h1.52
  text "0.086mm" at -21.439,64.196 h1.52
  text "3.8" at -4.934,64.196 h1.52
  text "15" at -84.16,61.148 h1.52
  text "Bottom Layer" at -73.749,61.148 h1.52
  text "Copper" at -50.133,61.148 h1.52
  text "0.012mm" at -21.439,61.148 h1.52
  text "16" at -84.16,58.1 h1.52
  text "Bottom Solder" at -73.749,58.1 h1.52
  text "Solder Resist" at -50.133,58.1 h1.52
  text "0.020mm" at -21.439,58.1 h1.52
  text "4.1" at -4.934,58.1 h1.52
  text "Manufacturing Notes" at 216.125,57.225 h3.05
  text "17" at -84.16,55.052 h1.52
  text "Bottom Overlay" at -73.749,55.052 h1.52
  text "Finished Board Thickness 1.0mm" at 216.125,52.725 h3.05
  text "Board to be FR4 Material" at 216.125,49.725 h3.05
  text "Board is 6 layer" at 216.125,46.725 h3.05
  text "Double sided resist in BLUE" at 216.125,43.725 h3.05
  text "Double sided silk screen in WHITE" at 216.125,40.725 h3.05
  text "Finish ENIG" at 216.125,37.725 h3.05
  text "All via in pad to be copper filled and flat pad" at 216.2,34.975 h3.05
  text "C" at -98.095,3.302 h1.78
  text "C" at 290.525,3.302 h1.78
  text "Copyright 2020" at 250.35,-24.425 h3.05
  text "ICOTEQ LTD" at 218.85,-24.5 h3.05
  text "Cambridge House" at 218.85,-27.425 h3.05
  text "1 Henry Street" at 218.85,-30.425 h3.05
  text "Bath" at 218.85,-33.425 h3.05
  text "BA1 1BT" at 218.85,-36.825 h3.05
  text "Website: www.icoteq.com" at 252.25,-43.725 h3.05
  text "Tel: 01225 618155" at 218.85,-43.925 h3.05
  text "Email: info@icoteq.com" at 218.65,-47.825 h3.05
  text "Project Number" at 214.15,-54.425 h3.05
  text "-" at 240.15,-54.425 h3.05
  text "Horizon Tag" at 240.15,-60.05 h3.05
  text "Project Name" at 214.15,-60.425 h3.05
  text "PCB Name" at 214.15,-66.425 h3.05
  text "Turtle Tracker" at 240.15,-66.425 h3.05
  text "D" at -98.095,-66.802 h1.78
  text "D" at 290.525,-66.802 h1.78
  text "Drawn by" at 214.15,-72.425 h3.05
  text "Craig Rackstraw" at 240.15,-72.425 h3.05
  text "Date" at 214.15,-78.425 h3.05
  text "3rd April 2020" at 240.15,-78.425 h3.05
  text "Issue" at 214.15,-84.425 h3.05
  text "4.0" at 240.15,-84.425 h3.05
  text "Document Name" at 214.15,-90.425 h3.05
  text "1" at -75.963,-98.349 h1.78
  text "2" at -26.924,-98.349 h1.78
  text "3" at 22.335,-98.349 h1.78
  text "4" at 71.628,-98.349 h1.78
  text "5" at 120.904,-98.349 h1.78
  text "6" at 169.926,-98.349 h1.78
  text "7" at 219.456,-98.349 h1.78
  text "8" at 268.478,-98.349 h1.78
